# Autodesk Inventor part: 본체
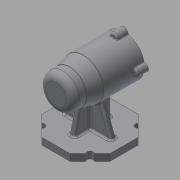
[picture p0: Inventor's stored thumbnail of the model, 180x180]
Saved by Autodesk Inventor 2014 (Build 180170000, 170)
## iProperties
Created: 2021-01
Part Number: 본체
Material: Generic
Document SubType Name: Modeling
Designer: kh
Density: 1 g/cm^3
Appearance: Default
Author: kh
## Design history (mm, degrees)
sketch "Sketch1" dims "d0" = 100
  geometry: L1 (20.711, 50)-(50, 20.711); L2 (50, 20.711)-(50, -20.711); L3 (50, -20.711)-(20.711, -50); L4 (20.711, -50)-(-20.711, -50); L5 (-20.711, -50)-(-50, -20.711); L6 (-50, -20.711)-(-50, 20.711); L7 (-50, 20.711)-(-20.711, 50); L8 (-20.711, 50)-(20.711, 50); 4 further points
  constraints: 16 end point, 2 coincident, 1 horizontal, 1 midpoint, 1 vertical alignment, 19 other
extrude "Extrusion1" new body sketch "Sketch1" distance "d1" = 10; taper "d2" = 0 deg
sketch "Sketch2"
  geometry: L1 (-50, 75)-(50, 75); L2 (50, 75)-(50, 105); L3 (50, 105)-(-10, 105); L4 (-10, 105)-(-30, 100); L5 (-30, 100)-(-50, 100); L6 (-50, 100)-(-50, 75); L7 (50, 96)-(35, 96); L8 (35, 96)-(35, 99); L9 (35, 99)-(-7, 99); L10 (-7, 99)-(-7, 96); L11 (-7, 96)-(-19, 96); L12 (-19, 96)-(-19, 92.5); L13 (-19, 92.5)-(-37, 92.5); L14 (-37, 92.5)-(-37, 91); L15 (-37, 91)-(-41, 91); L16 (-41, 91)-(-41, 85.5); L17 (-41, 85.5)-(-44, 85.5); L18 (-44, 85.5)-(-44, 75); L19 (50, 0)-(50, 10) reference; 1 further point
  constraints: 36 end point, 11 parallel, 4 perpendicular, 2 collinear, 2 point on line, 1 horizontal
  dimensions: "d3" = 75 vertical distance of point (0, 0) L1.end; "d4" = 60 diameter of L3 L1; "d5" = 100 distance between parallel lines of L2 L6; "d6" = 20 distance from line of L4.end L6; "d7" = 40 horizontal distance of L3.end L5.end; "d8" = 50 diameter of L5 L1; "d9" = 15 distance of L7.start L7.end; "d10" = 3 distance of L16.end L17.end; "d11" = 4 distance of L14.end L15.end; "d12" = 18 distance of L12.end L13.end; "d13" = 12 distance of L10.end L11.end; "d14" = 42 distance of L8.end L9.end; "d15" = 42 diameter of L7 L1; "d16" = 48 diameter of L9 L1; "d17" = 42 diameter of L11 L1; "d18" = 21 diameter of L17 L1; "d19" = 32 diameter of L15 L1; "d20" = 35 diameter of L13 L1
revolve "Revolution1" sketch "Sketch2" stored, may be unused: angle "d21" = 90 deg
sketch "Sketch3"
  geometry: L1 (50, 10)-(20.711, 10) reference; L2 (27, 10)-(27, 32.649); 1 further point
  constraints: 2 end point, 1 perpendicular, 1 point on line
  dimensions: "d22" = 23 distance of L1.start L2.start
feature "Rib1" sketch "Sketch3" dims "d23" = 1, "d24" = 8, "d25" = 0, "d26" = 0, "d27" = 1, "d28" = 1
sketch "Sketch4"
  geometry: L1 (-20.711, 10)-(-50, 10) reference; L2 (20.711, 10)-(-20.711, 10) reference; L3 (-27, 10)-(-21.326, 39.189); 1 further point
  constraints: 2 end point, 1 point on line
  dimensions: "d29" = 101 deg angle of L1 L3; "d30" = 23 distance of L1.end L3.start
feature "Rib2" sketch "Sketch4" dims "d31" = 1, "d32" = 8, "d33" = 0, "d34" = 0, "d35" = 1, "d36" = 1
sketch "Sketch5"
  geometry: L1 (50, 10)-(20.711, 10) reference; L2 (-20.711, 10)-(-50, 10) reference; L3 (-35, 10)-(-25.925, 34.933); L4 (35, 10)-(27.063, 31.806); 1 further point
  constraints: 4 end point, 2 point on line
  dimensions: "d37" = 15 distance of L1.start L4.start; "d38" = 110 deg angle of L1 L4; "d39" = 15 distance of L2.end L3.start; "d40" = 110 deg angle of L2 L3
feature "Rib3" dims "d41" = 1, "d42" = 8, "d43" = 0, "d44" = 0, "d45" = 1, "d46" = 1
feature "Rib4" dims "d47" = 1, "d48" = 8, "d49" = 0, "d50" = 0, "d51" = 1, "d52" = 1
sketch "Sketch6"
  geometry: L1 (0, 0)-(0, -30); C1 r 6 at (0, -30); 1 further point
  constraints: 2 end point, 1 centre point, 1 coincident, 1 vertical, 1 vertical alignment, 1 other
  dimensions: "d53" = 12 diameter of C1
extrude "Extrusion2" join sketch "Sketch6" distance "d54" = 16; taper "d55" = 0 deg
hole "Hole1" diameter "d58" = 3.242; stored, may be unused: countersink angle "d62" = 90 deg, drill point angle "d64" = 118 deg; dims "d56" = 10, "d57" = 10, "d59" = 8, "d60" = 4, "d61" = 2, "d63" = 10
pattern_circular "Circular Pattern1" dims angle "d66" = 360 deg
fillet "Fillet1" dims "d68" = 3
fillet "Fillet2" dims "d69" = 3
fillet "Fillet3" dims "d70" = 10
fillet "Fillet4" dims "d71" = 1
fillet "Fillet5" dims "d72" = 3
fillet "Fillet6" dims "d73" = 3
fillet "Fillet7" dims "d74" = 3
fillet "Fillet8" dims "d75" = 0.3
fillet "Fillet9" dims "d76" = 3
chamfer "Chamfer1" distance "d77" = 1; stored, may be unused: second distance "d78" = 2, angle "d79" = 45 deg
sketch "Sketch7"
  geometry: L1 (-20.711, -50)-(-50, -20.711) reference; L2 (0, 0)-(-35.355, -35.355); C1 r 4.5 at (-35.355, -35.355)
  constraints: 2 end point, 1 centre point, 1 coincident, 1 midpoint
  dimensions: "d80" = 9 diameter of C1
extrude "Extrusion3" cut sketch "Sketch7" stored distance "d81" = 16; taper "d82" = 0 deg
pattern_circular "Circular Pattern2" dims angle "d84" = 360 deg
body "Solid1"
